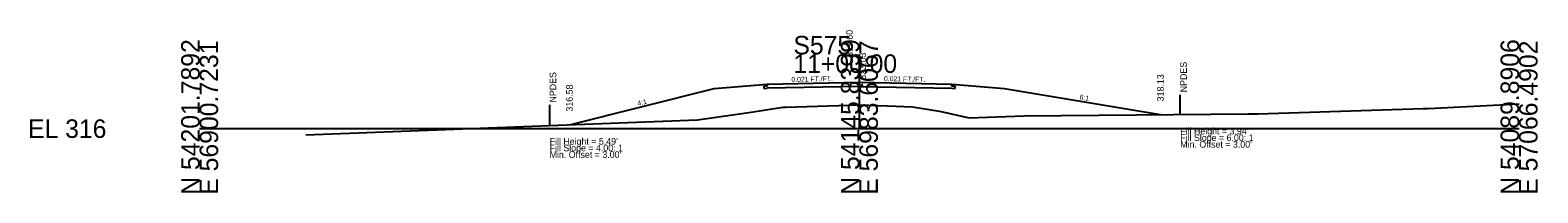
# Model space of a CAD drawing. Extents: x 10119 to 10347, y 94341 to 98867.
# Drawn here: x 10118.6 to 10347.2, y 94841.1 to 94865.7 of the extents above; entities that cross this region are included whole.
import ezdxf

# ---------------------------------------------------------------- set-up
doc = ezdxf.new("R2010")
doc.units = 0
for name, color, linetype in [('Level 10', 7, 'Continuous'), ('Level 11', 7, 'Continuous'), ('Level 12', 7, 'Continuous'), ('Level 32', 7, 'Continuous'), ('Level 33', 7, 'Continuous'), ('Level 50', 7, 'Continuous'), ('Level 55', 7, 'Continuous'), ('Level 59', 7, 'Continuous'), ('Level 6', 7, 'Continuous'), ('Level 60', 7, 'Continuous'), ('Level 63', 7, 'Continuous'), ('Level 7', 7, 'Continuous')]:
    doc.layers.add(name, color=color, linetype=linetype)

msp = doc.modelspace()

# ---------------------------------------------------------------- linework, layer by layer
at = {"layer": 'Level 11'}
for p, q in [((10230.31, 94857.25), (10229.81, 94857.24)), ((10229.81, 94857.24), (10229.81, 94856.9)), ((10229.81, 94856.9), (10230.31, 94856.91)), ((10230.31, 94857.54), (10230.31, 94857.25)), ((10258.31, 94857.25), (10258.31, 94857.54)), ((10258.81, 94857.24), (10258.31, 94857.25)), ((10258.31, 94856.91), (10258.81, 94856.9)), ((10258.81, 94856.9), (10258.81, 94857.24))]:
    msp.add_line(p, q, dxfattribs=at)
at = {"layer": 'Level 12'}
for q in [(10230.31, 94856.91), (10258.31, 94856.91)]:
    msp.add_line((10244.31, 94857.21), q, dxfattribs=at)
at = {"layer": 'Level 55'}
for p, q in [((10292.95, 94852.94), (10292.95, 94855.94)), ((10197.36, 94854.39), (10197.36, 94851.39))]:
    msp.add_line(p, q, dxfattribs=at)
at = {"layer": 'Level 59'}
for p, q in [((10230.31, 94857.54), (10244.31, 94857.84)), ((10244.31, 94857.84), (10258.31, 94857.54))]:
    msp.add_line(p, q, dxfattribs=at)
at = {"layer": 'Level 6'}
for p, q in [((10222.31, 94856.88), (10230.31, 94857.54)), ((10258.31, 94857.54), (10266.31, 94856.88))]:
    msp.add_line(p, q, dxfattribs=at)
at = {"layer": 'Level 60'}
for p, q in [((10330.54, 94853.88), (10344.31, 94854.55)), ((10219.79, 94852.13), (10227.58, 94853.24)), ((10227.58, 94853.24), (10232.72, 94854.07)), ((10232.72, 94854.07), (10233.14, 94854.04)), ((10233.14, 94854.04), (10244.36, 94854.41)), ((10244.36, 94854.41), (10249.89, 94854.21)), ((10249.89, 94854.21), (10252.34, 94854.09)), ((10252.34, 94854.09), (10256.45, 94853.44)), ((10256.45, 94853.44), (10260.96, 94852.47)), ((10260.96, 94852.47), (10269.27, 94852.77)), ((10269.27, 94852.77), (10303.24, 94853.05)), ((10303.24, 94853.05), (10304.02, 94853.05)), ((10304.02, 94853.05), (10304.72, 94853.06)), ((10304.72, 94853.06), (10329.75, 94853.86)), ((10329.75, 94853.86), (10330.54, 94853.88)), ((10160.42, 94849.87), (10219.79, 94852.13))]:
    msp.add_line(p, q, dxfattribs=at)
at = {"layer": 'Level 63'}
for p, q in [((10244.31, 94850.81), (10244.31, 94862.04)), ((10144.31, 94850.81), (10244.31, 94850.81)), ((10244.31, 94850.81), (10344.31, 94850.81))]:
    msp.add_line(p, q, dxfattribs=at)
at = {"layer": 'Level 7'}
for p, q in [((10200.36, 94851.39), (10222.31, 94856.88)), ((10266.31, 94856.88), (10289.95, 94852.94))]:
    msp.add_line(p, q, dxfattribs=at)

# ---------------------------------------------------------------- texts
at = {"layer": 'Level 10'}
msp.add_text('319.60', height=1, rotation=90, dxfattribs=at).set_placement((10243.31, 94861.66))
at = {"layer": 'Level 32'}
for s, rotation, p in [('0.021 FT./FT.', 1.1916, (10234.02, 94857.87)), ('0.021 FT./FT.', 358.8084, (10248.03, 94858.01)), ('4:1', 14.0362, (10210.76, 94854.25)), ('6:1', 350.5377, (10277.65, 94855.24))]:
    msp.add_text(s, height=0.75, rotation=rotation, dxfattribs=at).set_placement(p)
at = {"layer": 'Level 33'}
for s, p in [('316.58', (10200.86, 94853.39)), ('318.13', (10290.45, 94854.94))]:
    msp.add_text(s, height=1, rotation=90, dxfattribs=at).set_placement(p)
at = {"layer": 'Level 50'}
for p in [(10198.36, 94854.39), (10293.95, 94855.94)]:
    msp.add_text(' NPDES', height=1, rotation=90, dxfattribs=at).set_placement(p)
for s, p in [("Fill Height = 3.94' ", (10292.95, 94849.94)), ('Fill Slope = 6.00: 1', (10292.95, 94848.94)), ("Fill Height = 5.49' ", (10197.36, 94848.39)), ('Fill Slope = 4.00: 1', (10197.36, 94847.39)), ("Min. Offset = 3.00' ", (10292.95, 94847.94)), ("Min. Offset = 3.00' ", (10197.36, 94846.39))]:
    msp.add_text(s, height=1, dxfattribs=at).set_placement(p)
at = {"layer": 'Level 59'}
msp.add_text(' 323.03', height=1, rotation=90, dxfattribs=at).set_placement((10245.31, 94857.84))
at = {"layer": 'Level 63'}
for s, p in [('N 54201.7892', (10144.31, 94840.81)), ('E 56900.7231', (10147.11, 94840.81)), ('N 54145.8399', (10244.31, 94840.81)), ('E 56983.6067', (10247.11, 94840.81)), ('N 54089.8906', (10344.31, 94840.81)), ('E 57066.4902', (10347.11, 94840.81))]:
    msp.add_text(s, height=2.8, rotation=90, dxfattribs=at).set_placement(p)
for s, p in [('S575', (10234.32, 94862.04)), ('11+00.00', (10234.31, 94859.24)), ('EL 316', (10118.31, 94849.41))]:
    msp.add_text(s, height=2.8, dxfattribs=at).set_placement(p)

doc.saveas('drawing.dxf')
